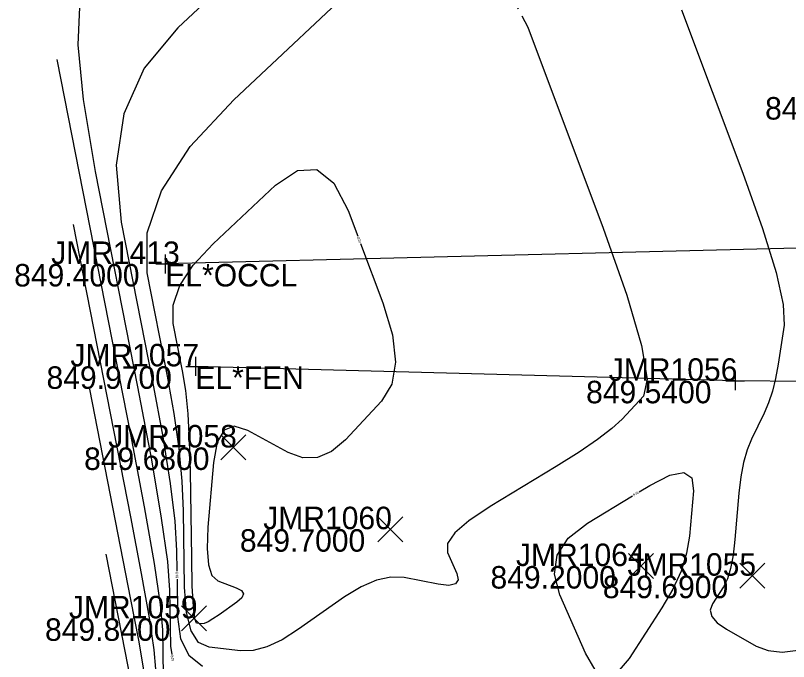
# Model space of a CAD drawing. Extents: x 1654928 to 1810050, y 486881 to 626330.
# Drawn here: x 1801296.64 to 1801337.91, y 489809.24 to 489843.71 of the extents above; entities that cross this region are included whole.
import ezdxf

# ---------------------------------------------------------------- set-up
doc = ezdxf.new("R2010")
doc.units = 0
for name, color, linetype in [('DT_X_Contour_Major', 7, 'Continuous'), ('DT_X_Contour_Minor', 7, 'Continuous'), ('RD_X_Fence', 7, 'Continuous'), ('SV_X_Occupation_Line', 7, 'Continuous'), ('SV_X_Random_Point', 7, 'Continuous'), ('SV_X_Shot_Marker', 7, 'Continuous'), ('SV_X_Text_Comment', 7, 'Continuous'), ('SV_X_Text_Elevation', 7, 'Continuous'), ('SV_X_Text_Name', 7, 'Continuous')]:
    doc.layers.add(name, color=color, linetype=linetype)

msp = doc.modelspace()

# ---------------------------------------------------------------- linework, layer by layer
at = {"layer": 'DT_X_Contour_Major'}
msp.add_lwpolyline([(1801304.537, 489808.484), (1801304.502, 489810.94), (1801304.386, 489812.282), (1801304.063, 489814.466), (1801303.532, 489817.491), (1801302.795, 489821.358), (1801298.872, 489841.368)], dxfattribs=at)
at = {"layer": 'DT_X_Contour_Minor'}
for points in [[(1801309.522, 489878.719), (1801308.373, 489873.608), (1801305.658, 489859.045), (1801304.685, 489854.189), (1801303.801, 489850.543), (1801303.006, 489848.108), (1801302.3, 489846.882), (1801300.538, 489845.228), (1801300.066, 489844.148), (1801299.969, 489842.147), (1801300.248, 489839.224), (1801300.904, 489835.382), (1801303.154, 489823.906), (1801303.894, 489820.001), (1801304.427, 489816.89), (1801304.753, 489814.574), (1801304.872, 489813.053), (1801304.915, 489810.056), (1801304.987, 489809.626)], [(1801326.553, 489878.166), (1801325.199, 489876.58), (1801323.908, 489874.965), (1801320.55, 489870.624), (1801319.395, 489868.918), (1801318.451, 489867.057), (1801317.717, 489865.041), (1801317.193, 489862.87), (1801316.075, 489856.874), (1801315.442, 489854.656), (1801314.381, 489852.501), (1801312.893, 489850.409), (1801310.978, 489848.38), (1801305.3, 489843.051), (1801303.515, 489840.904), (1801302.419, 489838.461), (1801302.011, 489835.72), (1801302.291, 489832.683), (1801303.956, 489824.188), (1801304.505, 489821.235), (1801304.902, 489818.747), (1801305.148, 489816.724), (1801305.243, 489815.165), (1801305.258, 489814.065)], [(1801306.975, 489810.002), (1801306.42, 489810.255), (1801306.018, 489810.873), (1801305.768, 489811.855), (1801305.67, 489813.202), (1801305.613, 489817.278), (1801305.543, 489818.874), (1801305.378, 489820.605), (1801305.116, 489822.47), (1801304.759, 489824.47), (1801303.678, 489829.985), (1801303.663, 489832.113), (1801304.428, 489834.361), (1801305.974, 489836.73), (1801308.3, 489839.219), (1801315.544, 489846.018), (1801318.11, 489847.747), (1801320.373, 489847.833), (1801322.335, 489846.278), (1801323.48, 489844.074)], [(1801332.191, 489844.017), (1801335.465, 489835.3), (1801336.524, 489832.342), (1801337.246, 489830.005), (1801337.631, 489828.288), (1801337.679, 489827.193), (1801337.356, 489825.1), (1801337.219, 489824.348), (1801337.049, 489823.663), (1801336.845, 489823.043), (1801336.609, 489822.49), (1801335.934, 489821.102), (1801335.702, 489820.532), (1801335.514, 489819.861), (1801335.369, 489819.09), (1801335.266, 489818.218), (1801335.051, 489815.76), (1801334.953, 489814.911), (1801334.819, 489814.207), (1801334.65, 489813.647), (1801334.446, 489813.233), (1801333.854, 489812.321), (1801333.734, 489811.98), (1801333.818, 489811.64), (1801334.105, 489811.302), (1801334.596, 489810.965), (1801336.177, 489810.07), (1801336.823, 489809.822), (1801337.575, 489809.75), (1801338.433, 489809.855)], [(1801323.673, 489843.701), (1801323.995, 489843.081), (1801328.02, 489832.366), (1801329.287, 489828.792), (1801330.068, 489826.107), (1801330.364, 489824.312), (1801330.175, 489823.406), (1801329.023, 489822.175), (1801328.48, 489821.671), (1801327.714, 489821.082), (1801326.725, 489820.408), (1801325.513, 489819.649), (1801321.983, 489817.512), (1801320.848, 489816.758), (1801320.09, 489816.1), (1801319.709, 489815.536), (1801319.705, 489815.068), (1801320.197, 489813.945), (1801320.273, 489813.593), (1801320.133, 489813.379), (1801319.778, 489813.304), (1801319.207, 489813.366), (1801317.395, 489813.717), (1801316.686, 489813.752), (1801315.917, 489813.591), (1801315.089, 489813.236), (1801314.201, 489812.687), (1801311.754, 489810.962), (1801310.873, 489810.405), (1801310.063, 489810.027), (1801309.324, 489809.829), (1801308.657, 489809.811), (1801306.975, 489810.002)], [(1801306.307, 489811.289), (1801306.211, 489811.515), (1801306.137, 489812.172), (1801306.082, 489813.258), (1801306.048, 489814.774), (1801305.983, 489819.39), (1801305.938, 489821.024), (1801305.853, 489822.462), (1801305.727, 489823.705), (1801305.561, 489824.753), (1801305.065, 489827.286), (1801305.058, 489828.264), (1801305.409, 489829.297), (1801306.12, 489830.385), (1801307.188, 489831.529), (1801310.517, 489834.653), (1801311.696, 489835.447), (1801312.736, 489835.487), (1801313.637, 489834.772), (1801314.4, 489833.303), (1801314.911, 489831.943)], [(1801304.132, 489808.827), (1801304.042, 489809.875), (1801303.789, 489811.578), (1801303.376, 489813.939), (1801302.8, 489816.956), (1801299.74, 489832.568)], [(1801315.058, 489831.55), (1801316.249, 489828.38), (1801316.765, 489826.668), (1801316.927, 489825.223), (1801316.733, 489824.047), (1801316.186, 489823.138), (1801314.252, 489821.071), (1801313.517, 489820.448), (1801312.762, 489820.129), (1801311.987, 489820.113), (1801311.191, 489820.401), (1801309.043, 489821.575), (1801308.324, 489821.798), (1801307.779, 489821.588), (1801307.408, 489820.944), (1801307.211, 489819.866), (1801306.917, 489816.414), (1801306.867, 489815.265), (1801306.938, 489814.404), (1801307.128, 489813.832), (1801307.439, 489813.549), (1801308.428, 489813.181), (1801308.708, 489813.029), (1801308.806, 489812.849), (1801308.723, 489812.64), (1801308.458, 489812.403), (1801307.509, 489811.735), (1801307.184, 489811.517), (1801306.923, 489811.364), (1801306.723, 489811.278), (1801306.587, 489811.257), (1801306.307, 489811.289)], [(1801303.516, 489808.691), (1801303.219, 489810.386), (1801302.806, 489812.554), (1801300.607, 489823.768)], [(1801329.932, 489818.298), (1801330.501, 489818.642), (1801331.581, 489819.189), (1801332.33, 489819.322), (1801332.748, 489819.04), (1801332.834, 489818.343), (1801332.623, 489815.934), (1801332.472, 489815.016), (1801332.176, 489814.071), (1801331.735, 489813.099), (1801331.15, 489812.1), (1801329.397, 489809.398)], [(1801329.397, 489809.398), (1801328.759, 489808.657), (1801328.157, 489808.46), (1801327.592, 489808.807), (1801327.064, 489809.697), (1801325.707, 489812.797), (1801325.417, 489813.909), (1801325.566, 489814.918), (1801326.153, 489815.826), (1801327.18, 489816.631), (1801329.573, 489818.08)], [(1801302.811, 489808.151), (1801301.474, 489814.968)], [(1801305.264, 489813.645), (1801305.292, 489811.629), (1801305.453, 489810.452), (1801305.899, 489809.574), (1801306.629, 489808.995)]]:
    msp.add_lwpolyline(points, dxfattribs=at)
at = {"layer": 'RD_X_Fence'}
msp.add_lwpolyline([(1801327.157, 489980.825), (1801341.337, 489952.815), (1801353.978, 489927.719), (1801368.649, 489898.399), (1801382.749, 489869.731), (1801399.284, 489836.538), (1801405.615, 489823.327), (1801393.757, 489823.044), (1801375.98, 489823.449), (1801361.092, 489823.97), (1801335.059, 489824.221), (1801306.244, 489824.992)], dxfattribs=at)
at = {"layer": 'SV_X_Occupation_Line'}
msp.add_lwpolyline([(1801323.637, 489975.339), (1801342.746, 489938.404), (1801356.309, 489913.548), (1801376.911, 489872.203), (1801387.619, 489838.687), (1801379.855, 489831.976), (1801347.713, 489831.536), (1801304.639, 489830.454)], dxfattribs=at)
at = {"layer": 'SV_X_Random_Point'}
for p, q in [((1801307.603, 489819.997), (1801308.936, 489821.332)), ((1801307.603, 489821.332), (1801308.936, 489819.997)), ((1801315.994, 489815.635), (1801317.327, 489816.97)), ((1801315.994, 489816.97), (1801317.327, 489815.635)), ((1801329.374, 489813.668), (1801330.707, 489815.003)), ((1801329.374, 489815.003), (1801330.707, 489813.668)), ((1801335.314, 489813.155), (1801336.647, 489814.49)), ((1801335.314, 489814.49), (1801336.647, 489813.155)), ((1801305.506, 489810.878), (1801306.84, 489812.213)), ((1801305.506, 489812.213), (1801306.84, 489810.878))]:
    msp.add_line(p, q, dxfattribs=at)
at = {"layer": 'SV_X_Shot_Marker'}
for p, q in [((1801304.639, 489830.954), (1801304.639, 489829.954)), ((1801304.139, 489830.454), (1801305.139, 489830.454)), ((1801304.639, 489830.454), (1801304.639, 489830.454)), ((1801306.244, 489825.492), (1801306.244, 489824.492)), ((1801305.744, 489824.992), (1801306.744, 489824.992)), ((1801306.244, 489824.992), (1801306.244, 489824.992)), ((1801335.059, 489824.721), (1801335.059, 489823.721)), ((1801334.559, 489824.221), (1801335.559, 489824.221)), ((1801335.059, 489824.221), (1801335.059, 489824.221))]:
    msp.add_line(p, q, dxfattribs=at)

# ---------------------------------------------------------------- texts
at = {"layer": 'DT_X_Contour_Minor'}
for s, rotation, p in [('850', 110.5857, (1801315.108, 489831.616)), ('849', 31.1953, (1801329.652, 489818.046)), ('849', 270.8059, (1801305.189, 489814.015)), ('849', 279.5328, (1801304.926, 489809.566))]:
    msp.add_text(s, height=0.14, rotation=rotation, dxfattribs=at).set_placement(p)
at = {"layer": 'SV_X_Text_Comment'}
for s, p in [('EL*OCCL', (1801304.639, 489829.254)), ('EL*FEN', (1801306.244, 489823.792))]:
    msp.add_text(s, height=1.2, dxfattribs=at).set_placement(p)
at = {"layer": 'SV_X_Text_Elevation'}
for s, p in [('849.7400', (1801336.659, 489838.159)), ('849.4000', (1801296.57, 489829.254)), ('849.9700', (1801298.298, 489823.792)), ('849.5400', (1801327.104, 489823.021)), ('849.6800', (1801300.305, 489819.464)), ('849.7000', (1801308.62, 489815.103)), ('849.2000', (1801322, 489813.135)), ('849.6900', (1801327.997, 489812.622)), ('849.8400', (1801298.218, 489810.346))]:
    msp.add_text(s, height=1.2, dxfattribs=at).set_placement(p)
at = {"layer": 'SV_X_Text_Name'}
for s, p in [('JMR1413', (1801298.546, 489830.454)), ('JMR1057', (1801299.574, 489824.992)), ('JMR1056', (1801328.314, 489824.221)), ('JMR1058', (1801301.59, 489820.664)), ('JMR1060', (1801309.867, 489816.303)), ('JMR1064', (1801323.361, 489814.335)), ('JMR1055', (1801329.311, 489813.823)), ('JMR1059', (1801299.494, 489811.546))]:
    msp.add_text(s, height=1.2, dxfattribs=at).set_placement(p)

doc.saveas('drawing.dxf')
